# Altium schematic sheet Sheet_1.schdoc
size 307 x 214 mm
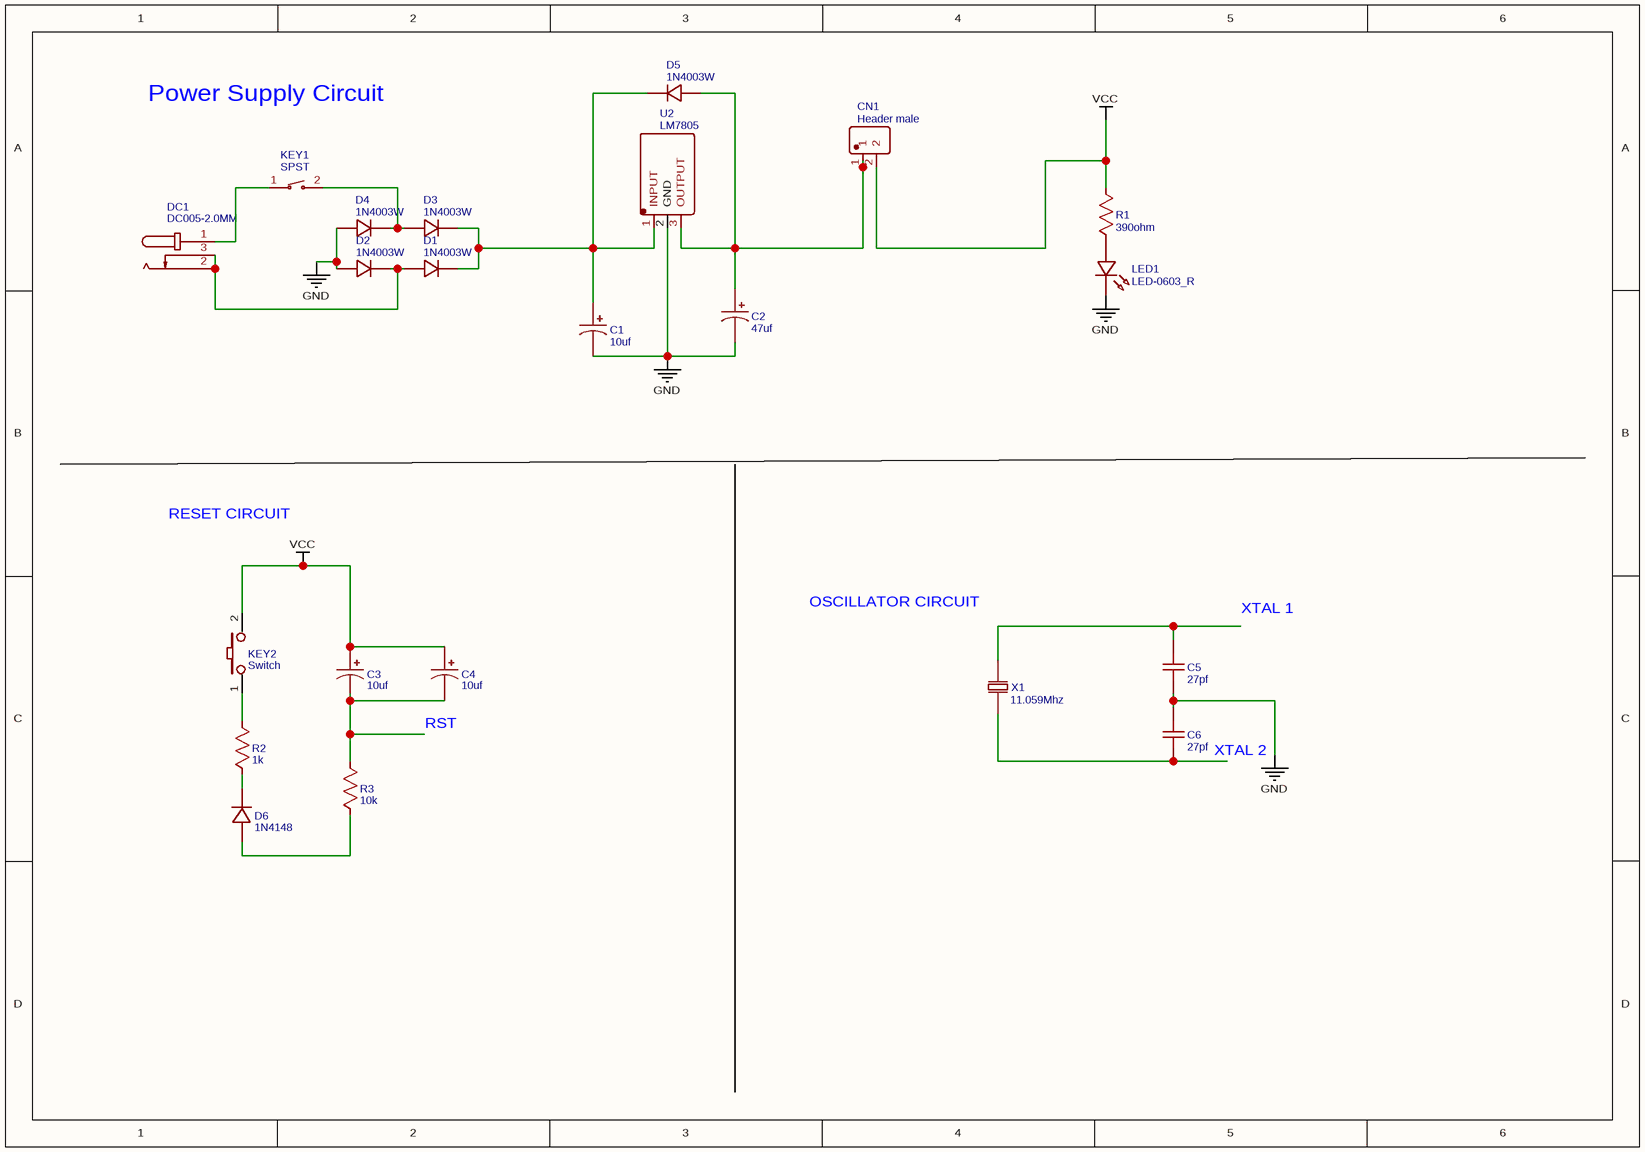
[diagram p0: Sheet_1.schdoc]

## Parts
C1  10uf  [CASE-A_3216]
C2  47uf  [CASE-A_3216]
C3  10uf  [CASE-A_3216]
C4  10uf  [CASE-A_3216]
C5  27pf  [C0603]
C6  27pf  [C0603]
CN1  Header male  [CONN-TH_2P-P4.00_VH2-HEADER2]
D1  1N4003W  [SOD-123FL_L2.7-W1.8-LS3.8-RD]
D2  1N4003W  [SOD-123FL_L2.7-W1.8-LS3.8-RD]
D3  1N4003W  [SOD-123FL_L2.7-W1.8-LS3.8-RD]
D4  1N4003W  [SOD-123FL_L2.7-W1.8-LS3.8-RD]
D5  1N4003W  [SOD-123FL_L2.7-W1.8-LS3.8-RD]
D6  1N4148  [SOD-323_L1.8-W1.3-LS2.5-RD]
DC1  DC005-2.0MM  [DC-IN-TH_DC005-T20]
KEY1  SPST  [KEY-SMD_L6.0-W3.6-LS8.0]
KEY2  Switch  [SW-SMD_L4.0-W2.9-LS5.0]
LED1  LED-0603_R  [LED0603_RED]
R1  390ohm  [R0603]
R2  1k  [R0603]
R3  10k  [R0603]
U2  LM7805  [TO-220IS_L10.16-W4.7-P2.54-L]
X1  11.059Mhz  [CRYSTAL-SMD_L3.2-W1.5-1]

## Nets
GND: C1.2 C2.2 C5.1 C6.2 D2.2(A) D4.2(A) LED1.2 U2.2(GND)
VCC: C3.1 C4.1 CN1.2 KEY2.2 R1.2
NetC1_1: C1.1 D1.1(K) D3.1(K) D5.1(K) U2.1(INPUT)
NetC2_1: C2.1 CN1.1 D5.2(A) U2.3(OUTPUT)
NetC3_2: C3.2 C4.2 R3.2
NetC5_2: C5.2 X1.2
NetC6_1: C6.1 X1.1
NetD1_2: D1.2(A) D2.1(K) DC1.2 DC1.3
NetD3_2: D3.2(A) D4.1(K) KEY1.2
NetD6_1: D6.1(K) R2.1
NetD6_2: D6.2(A) R3.1
NetDC1_1: DC1.1 KEY1.1
NetKEY2_1: KEY2.1 R2.2
NetLED1_1: LED1.1 R1.1

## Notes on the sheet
- Power Supply Circuit
- RESET CIRCUIT
- OSCILLATOR CIRCUIT
- XTAL 1
- (near C4) RST
- (near C6) XTAL 2

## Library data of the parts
C1 C3 C4 = 10uf: nameAlias: Value(F); Contributor: LCEDA_Lib
C2 = 47uf: nameAlias: Value(F); Contributor: LCEDA_Lib
C5 C6 = 27pf: nameAlias: Value(F); Contributor: LCEDA_Lib
CN1 = Header male: BOM_Manufacturer: null; BOM_Manufacturer Part: VH2-Header2; Contributor: LCSC
D1-D5 = 1N4003W: BOM_Manufacturer: Shandong Jingdao Microelectronics; Contributor: LCSC
D6 = 1N4148: BOM_Manufacturer: Tak Cheong; BOM_Manufacturer Part: TC1N4148WS; Contributor: LCSC
DC1 = DC005-2.0MM: BOM_Manufacturer: SOFNG
KEY1 = SPST: BOM_Manufacturer: null; BOM_Manufacturer Part: SW-SPST-SMT3*6*2.5贴片按钮; Contributor: LCSC
KEY2 = Switch: BOM_Manufacturer: ReliaPro; BOM_Manufacturer Part: Switch3x4x2
LED1 = LED-0603_R: BOM_Manufacturer: EVERLIGHT(台湾亿光); BOM_Manufacturer Part: 19-217/R6C-AL1M2VY/3T; Contributor: LCEDA_01
R1 = 390ohm: nameAlias: Value(Ω); Contributor: LCEDA_Lib
R2 = 1k: nameAlias: Value(Ω); Contributor: LCEDA_Lib
R3 = 10k: nameAlias: Value(Ω); Contributor: LCEDA_Lib
U2 = LM7805: BOM_Manufacturer: Unisonic Tech; BOM_Manufacturer Part: LM7805L-TA3-T; Contributor: LCSC
X1 = 11.059Mhz: BOM_Manufacturer Part: 贴片无源晶振32.768KHZ 3.2*1.5 3215; Contributor: LCSC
